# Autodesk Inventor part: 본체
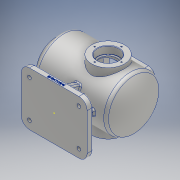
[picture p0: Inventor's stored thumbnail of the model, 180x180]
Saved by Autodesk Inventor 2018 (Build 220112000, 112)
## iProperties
Created: 2021-11
Part Number: 본체
Material: 알루미늄 6061
Document SubType Name: Modeling
Designer: na
Density: 2.7 g/cm^3
Appearance: 알루미늄 - 평지
Mass: 3541.09 g
Surface Area: 2403.18 cm^2
Volume: 1311.51 cm^3
Author: na
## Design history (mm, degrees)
sketch "스케치1"
  geometry: L1 (60, -65)-(-60, -65); L2 (-80, -45)-(-80, 45); L3 (-60, 65)-(60, 65); L4 (80, 45)-(80, -45); A1 r 20 centre (60, -45) between (60, -65) and (80, -45); A2 r 20 centre (-60, -45) between (-80, -45) and (-60, -65); A3 r 20 centre (-60, 45) between (-60, 65) and (-80, 45); A4 r 20 centre (60, 45) between (80, 45) and (60, 65); 6 further points
  constraints: 8 end point, 8 point on circle, 8 tangent, 6 point on line, 4 centre point, 2 midpoint, 2 parallel, 1 horizontal, 1 horizontal alignment, 1 perpendicular, 1 vertical alignment
  dimensions: "d0" = 160 distance of point (-80, 65) point (80, 65); "d1" = 130 distance of point (-80, -65) point (-80, 65); "d2" = 20 radius of A1; "d3" = 20 radius of A2; "d4" = 20 radius of A3; "d5" = 20 radius of A4
extrude "돌출1" new body sketch "스케치1" distance "d6" = 14; taper "d7" = 0 deg
sketch "스케치2"
  geometry: L1 (-80, 45)-(-80, -45) reference; L2 (-60, -65)-(60, -65) reference; L3 (80, -45)-(80, 45) reference; L4 (60, 65)-(-60, 65) reference; A1 r 20 centre (-60, -45) between (-80, -45) and (-60, -65) reference; A2 r 20 centre (60, -45) between (60, -65) and (80, -45) reference; A3 r 20 centre (60, 45) between (80, 45) and (60, 65) reference; A4 r 20 centre (-60, 45) between (-60, 65) and (-80, 45) reference; 1 further point
hole "구멍1" sketch "스케치2" at (-60, 45), (60, -45), (60, 45), (-60, -45) diameter "d8" = 9; stored, may be unused: countersink angle "d12" = 90 deg, drill point angle "d14" = 118 deg; dims "d9" = 6, "d10" = 18, "d11" = 2, "d13" = 8
sketch "스케치3"
  geometry: L1 (-110, 114)-(110, 114); L2 (-110, 114)-(-110, 146.5); L3 (-110, 146.5)-(-110, 161.5); L4 (-110, 161.5)-(-100, 161.5); L5 (-100, 161.5)-(-100, 179); L6 (-100, 179)-(75.993, 179); L7 (-110, 114)-(100, 114); L8 (-80, 0)-(-80, 14) reference; A1 r 100 centre (0, 114) between (100, 114) and (75.993, 179); 1 further point
  constraints: 14 end point, 2 horizontal, 2 perpendicular, 2 point on circle, 1 centre point, 1 midpoint, 1 point on line, 1 tangent, 1 vertical
  dimensions: "d15" = 114 distance from line of L1 point (0, 0); "d16" = 32.5 distance of L1.start L2.end; "d18" = 10 distance of L3.end L4.end; "d23" = 100 distance of L7.end A1.centre; "d25" = 65 distance from line of L7.end L6; "d26" = 130 diameter of L6 L1; "d27" = 95 diameter of L4 L1; "d35" = 30 distance between parallel lines of L8 L2
revolve "회전1" sketch "스케치3" stored, may be unused: angle "d28" = 90 deg
sketch "스케치4"
  geometry: L1 (-126.291, 114)-(138.957, 114); L2 (-100, 179)-(75.993, 179) reference; L3 (-85, 169)-(71.239, 169); L4 (-110, 146.5)-(-85, 146.5); L5 (-85, 146.5)-(-85, 169); L6 (-110, 66.5)-(-110, 161.5) reference; L7 (-110, 146.5)-(-110, 114); L8 (-110, 114)-(90, 114); A1 r 100 centre (0, 114) between (75.993, 49) and (75.993, 179) reference; A2 r 90 centre (0, 114) between (90, 114) and (71.239, 169); 1 further point
  constraints: 12 end point, 2 horizontal, 2 point on circle, 2 point on line, 1 centre point, 1 midpoint, 1 parallel, 1 perpendicular
  dimensions: "d29" = 114 distance from line of L1 point (0, 0); "d30" = 10 radial gap between concentric circles of A1 A2; "d31" = 10 distance between parallel lines of L3 L2; "d32" = 25 distance of L4.start L4.end; "d33" = 65 diameter of L4 L1
revolve "회전2" sketch "스케치4" stored, may be unused: angle "d34" = 90 deg
sketch "스케치6"
  geometry: L1 (58.485, 33.809)-(14, 50); L2 (58.485, -33.809)-(14, -50); L3 (14, 54)-(14, 36) reference; L4 (14, -36)-(14, -54) reference; L5 (14, 45)-(14, 65) reference; L6 (14, -65)-(14, -45) reference; L7 (14, 50)-(14, -50); L8 (12, -54)-(12, -36) reference; A1 r 65 centre (114, 0) between (58.485, 33.809) and (58.485, -33.809) reference; 1 further point
  constraints: 6 end point, 2 point on circle, 2 point on line, 1 parallel
  dimensions: "d36" = 50 vertical distance of point (0, 0) L1.end; "d37" = 100 distance of L2.end L1.end; "d38" = 110 deg angle of L5 L1; "d39" = 110 deg angle of L6 L2
extrude "돌출2" join sketch "스케치6" stored distance "d40" = 14; taper "d41" = 0 deg
sketch "스케치7"
  geometry: L1 (-45.794, 53.03)-(-60, 14); L2 (-69, 14)-(-51, 14) reference
  constraints: 2 end point
  dimensions: "d49" = 70 deg angle of L2 L1
feature "리브1" sketch "스케치7" dims "d50" = 1, "d51" = 14, "d52" = 0, "d53" = 0, "d54" = 1, "d55" = 1
node "작업 평면1"
sketch "스케치8"
  geometry: L1 (-110, 66.5)-(-110, 161.5) reference; L2 (80, 0)-(60, 0) reference; C1 r 40 at (17, 114)
  constraints: 1 centre point
  dimensions: "d57" = 80 diameter of C1; "d105" = 127 distance from line of C1.centre L1; "d106" = 114 distance from line of L2 C1.centre
extrude "돌출3" join sketch "스케치8" stored distance "d59" = 14; taper "d60" = 0 deg
sketch "스케치10"
  geometry: C1 r 40 at (0, 0) reference; 1 further point
hole "구멍2" sketch "스케치10" at (0, 0) diameter "d61" = 42; stored, may be unused: countersink angle "d65" = 90 deg, drill point angle "d67" = 118 deg; dims "d62" = 6, "d63" = 52, "d64" = 18, "d66" = 8
sketch "스케치11"
  geometry: C1 r 26 at (0, 0) reference; C2 r 40 at (0, 0) reference; 2 further points
  constraints: 1 vertical alignment
  dimensions: "d68" = 32.5 distance of C1.centre point (0, 32.5)
hole "구멍3" sketch "스케치11" at (0, 32.5) diameter "d69" = 3.242; stored, may be unused: countersink angle "d73" = 90 deg, drill point angle "d75" = 118 deg; dims "d70" = 11, "d71" = 52, "d72" = 18, "d74" = 13
node "작업 평면2"
sketch "스케치12"
  geometry: L1 (45, -30)-(-45, -30); L2 (-60, -15)-(-60, 15); L3 (-45, 30)-(45, 30); L4 (60, 15)-(60, -15); L5 (110, 47.5)-(110, -47.5) reference; A1 r 15 centre (45, -15) between (45, -30) and (60, -15); A2 r 15 centre (45, 15) between (60, 15) and (45, 30); A3 r 15 centre (-45, 15) between (-45, 30) and (-60, 15); A4 r 15 centre (-45, -15) between (-60, -15) and (-45, -30); 5 further points
  constraints: 8 end point, 8 point on circle, 8 point on line, 8 tangent, 4 centre point, 2 parallel, 1 horizontal, 1 perpendicular
  dimensions: "d81" = 120 distance of point (-60, 30) point (60, 30); "d82" = 60 distance of point (-60, -30) point (-60, 30); "d83" = 50 distance between parallel lines of L4 L5; "d84" = 30 distance from line of point (0, 0) L3; "d87" = 15 radius of A1; "d88" = 15 radius of A2; "d89" = 15 radius of A3; "d90" = 15 radius of A4
extrude "돌출4" join sketch "스케치12" stored distance "d85" = 14; taper "d86" = 0 deg
sketch "스케치13"
  geometry: L1 (-60, 15)-(-60, -15) reference; L2 (-45, 30)-(45, 30) reference; L3 (60, -15)-(60, 15) reference; L4 (45, -30)-(-45, -30) reference; L5 (45, 20)-(-45, 20); L6 (-50, 15)-(-50, -15); L7 (-45, -20)-(45, -20); L8 (50, -15)-(50, 15); 1 further point
  constraints: 8 end point, 7 parallel, 16 other
  dimensions: "d91" = 10 distance between parallel lines of L2 L5
extrude "돌출5" cut sketch "스케치13" stored distance "d92" = 14; taper "d93" = 0 deg
sketch "스케치14"
  geometry: L1 (50, 15)-(50, -15) reference; L2 (45, -20)-(-45, -20) reference; L3 (-50, -15)-(-50, 15) reference; L4 (-45, 20)-(45, 20) reference; L5 (-60, 15)-(-60, -15) reference; L6 (-45, -30)-(45, -30) reference; L7 (60, -15)-(60, 15) reference; L8 (45, 30)-(-45, 30) reference; A1 r 15 centre (-45, -15) between (-60, -15) and (-45, -30) reference; A2 r 15 centre (45, -15) between (45, -30) and (60, -15) reference; A3 r 15 centre (45, 15) between (60, 15) and (45, 30) reference; A4 r 15 centre (-45, 15) between (-45, 30) and (-60, 15) reference; 5 further points
  constraints: 2 horizontal alignment, 2 vertical alignment, 4 other
  dimensions: "d94" = 25 distance of point (0, 0) point (0, 25); "d95" = 55 distance of point (0, 0) point (-55, 0); "d96" = 55 distance of point (0, 0) point (55, 0); "d97" = 25 distance of point (0, -25) point (0, 0)
hole "구멍4" sketch "스케치14" at (0, 25), (-55, 0), (0, -25), (55, 0) diameter "d98" = 3.242; stored, may be unused: countersink angle "d102" = 90 deg, drill point angle "d104" = 118 deg; dims "d99" = 9, "d100" = 52, "d101" = 18, "d103" = 11
chamfer "모따기1" distance "d107" = 1; stored, may be unused: second distance "d108" = 2, angle "d109" = 45 deg
chamfer "모따기2" distance "d110" = 1; stored, may be unused: second distance "d111" = 2, angle "d112" = 45 deg
fillet "모깎기1" dims "d113" = 3
fillet "모깎기2" dims "d114" = 3
fillet "모깎기3" dims "d115" = 3
fillet "모깎기4" dims "d116" = 10
fillet "모깎기5" dims "d117" = 10
fillet "모깎기6" dims "d118" = 3
fillet "모깎기7" dims "d119" = 3
sketch "스케치15"
  geometry: 1 further point
fillet "모깎기8" dims "d120" = 3
sketch "스케치16"
  geometry: L1 (0, 0)-(120, 0) reference; 3 further points
  constraints: 1 midpoint, 1 vertical alignment, 1 other
  dimensions: "d121" = 5 distance from line of L1 point (60, 5)
feature "엠보싱1" sketch "스케치16" dims "d81" = 120, "d122" = 0.5, "d123" = 0
sketch "스케치17"
  geometry: C1 r 47.5 at (0, 0) reference; 2 further points
  constraints: 1 vertical alignment
  dimensions: "d124" = 40 distance of C1.centre point (0, 40)
hole "구멍5" sketch "스케치17" at (0, 40) diameter "d125" = 3.242; stored, may be unused: countersink angle "d129" = 90 deg, drill point angle "d131" = 118 deg; dims "d126" = 11, "d127" = 52, "d128" = 18, "d130" = 13
fillet "모깎기9" dims "d135" = 0.3
node "솔리드1"
mirror "미러1"
pattern_circular "원형 패턴1" dims angle "d77" = 360 deg
mirror "미러2"
mirror "미러3"
pattern_circular "원형 패턴2" dims angle "d133" = 360 deg
node "투영된 루프1"
node "투영된 루프2"
node "투영된 루프3"
node "투영된 루프4"
other parameters: "d56" = 75, "d79" = 184
